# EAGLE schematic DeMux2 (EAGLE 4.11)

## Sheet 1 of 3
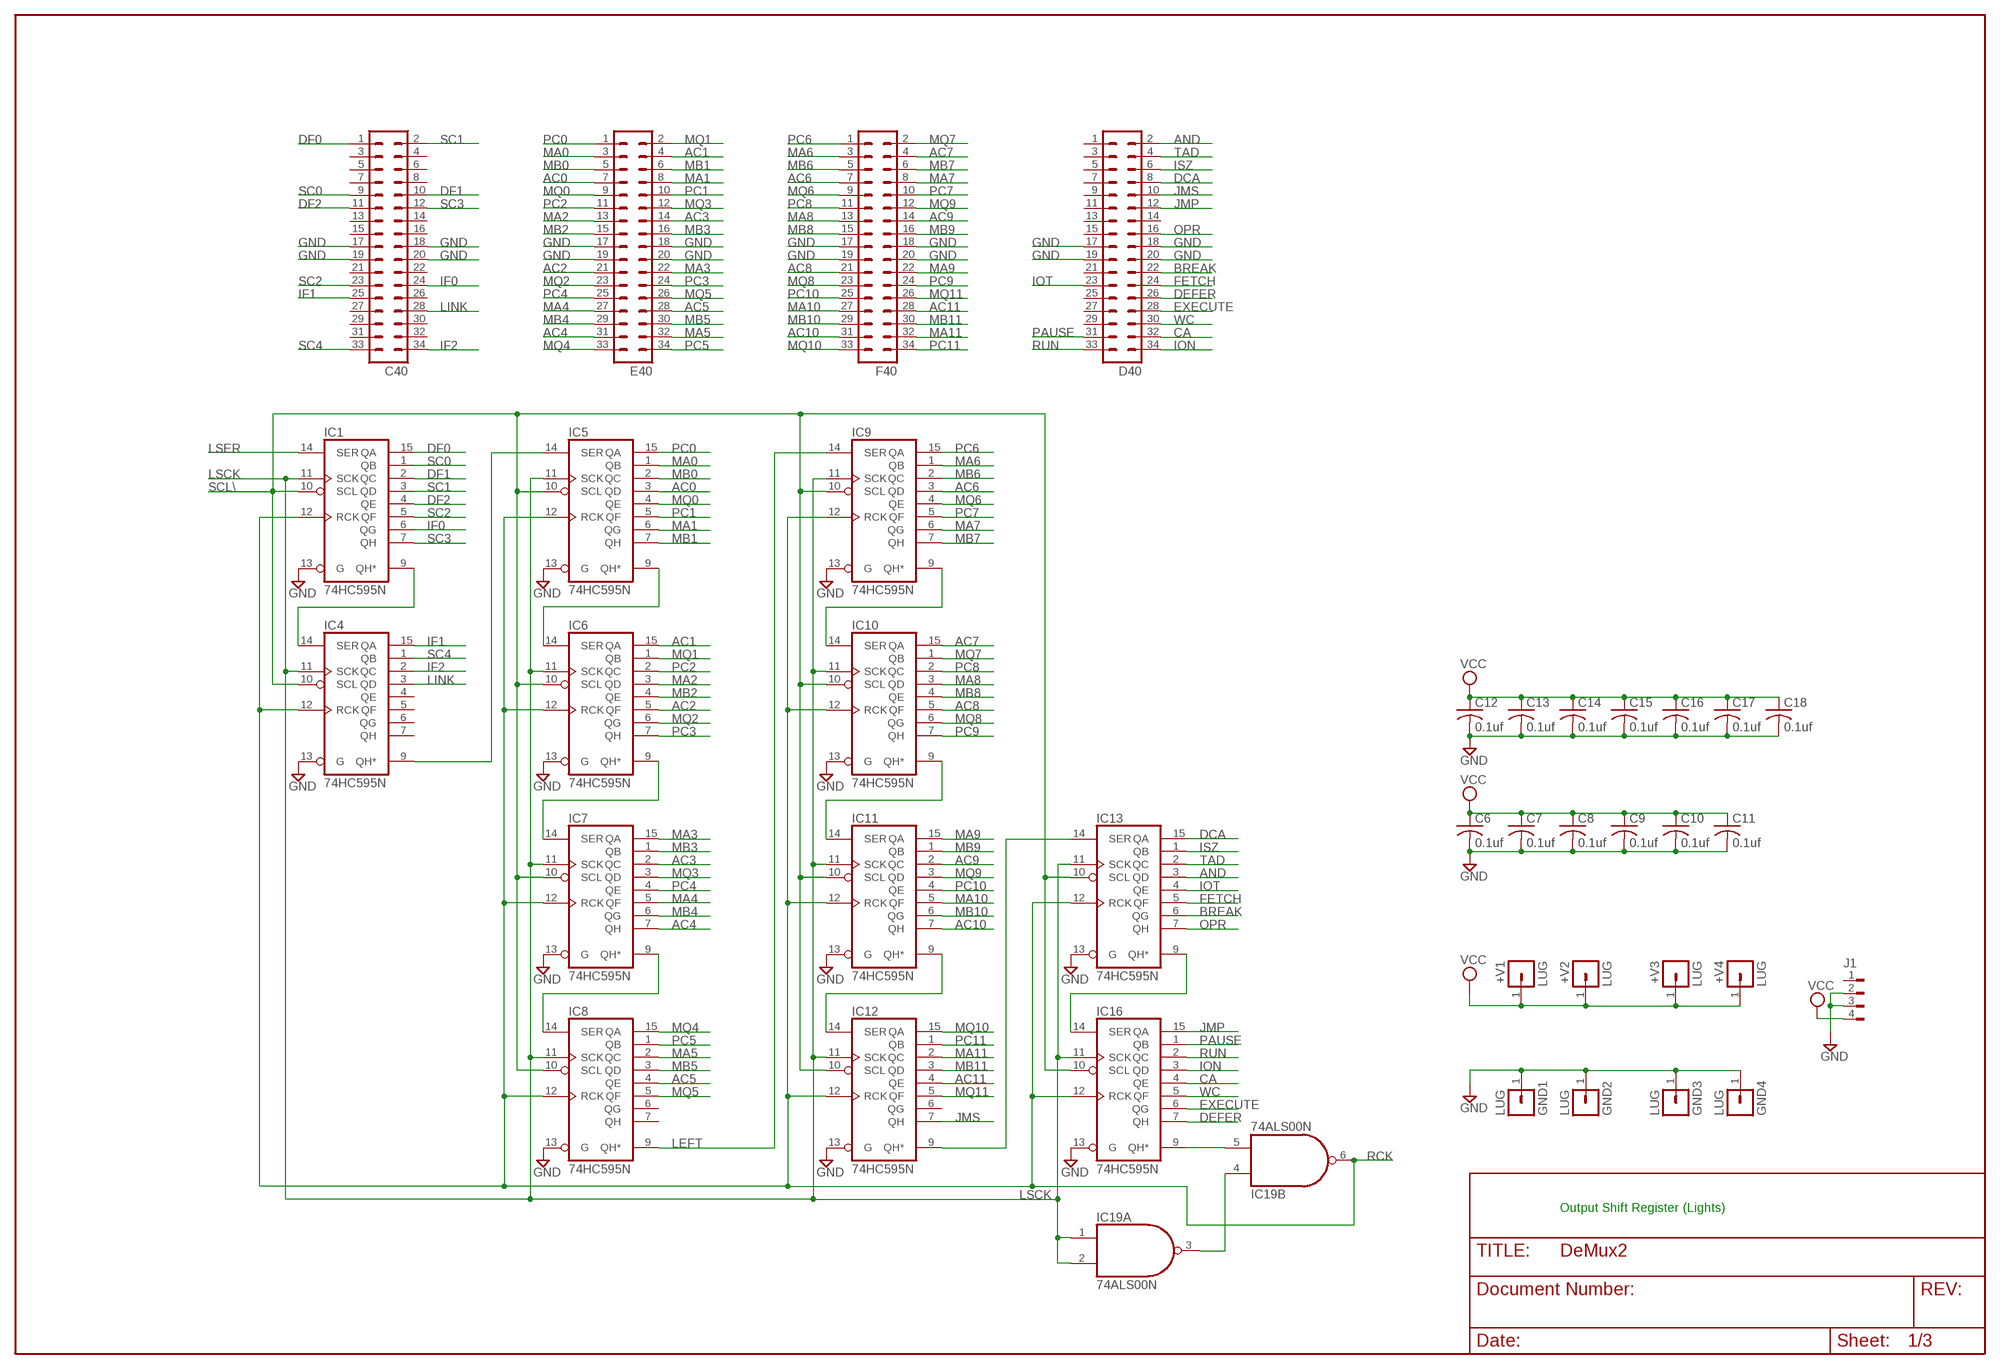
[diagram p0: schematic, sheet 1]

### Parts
+V1  LUG  [SPADELUG]
+V2  LUG  [SPADELUG]
+V3  LUG  [SPADELUG]
+V4  LUG  [SPADELUG]
C6  0.1uf  C-US050-025X075  [C050-025X075]
C7  0.1uf  C-US050-025X075  [C050-025X075]
C8  0.1uf  C-US050-025X075  [C050-025X075]
C9  0.1uf  C-US050-025X075  [C050-025X075]
C10  0.1uf  C-US050-025X075  [C050-025X075]
C11  0.1uf  C-US050-025X075  [C050-025X075]
C12  0.1uf  C-US050-025X075  [C050-025X075]
C13  0.1uf  C-US050-025X075  [C050-025X075]
C14  0.1uf  C-US050-025X075  [C050-025X075]
C15  0.1uf  C-US050-025X075  [C050-025X075]
C16  0.1uf  C-US050-025X075  [C050-025X075]
C17  0.1uf  C-US050-025X075  [C050-025X075]
C18  0.1uf  C-US050-025X075  [C050-025X075]
C40  MA17-2  [MA17-2]
D40  MA17-2  [MA17-2]
E40  MA17-2  [MA17-2]
F40  MA17-2  [MA17-2]
GND1  LUG  [SPADELUG]
GND2  LUG  [SPADELUG]
GND3  LUG  [SPADELUG]
GND4  LUG  [SPADELUG]
IC1  74HC595N  74LS595N  [DIL16]
IC4  74HC595N  74LS595N  [DIL16]
IC5  74HC595N  74LS595N  [DIL16]
IC6  74HC595N  74LS595N  [DIL16]
IC7  74HC595N  74LS595N  [DIL16]
IC8  74HC595N  74LS595N  [DIL16]
IC9  74HC595N  74LS595N  [DIL16]
IC10  74HC595N  74LS595N  [DIL16]
IC11  74HC595N  74LS595N  [DIL16]
IC12  74HC595N  74LS595N  [DIL16]
IC13  74HC595N  74LS595N  [DIL16]
IC16  74HC595N  74LS595N  [DIL16]
IC19  74ALS00N  [DIL14]
J1  FLOPPY-4  [FLOPPY-4]

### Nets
AC0: E40.7 IC5.3(QD)
AC1: E40.4 IC6.15(QA)
AC2: E40.21 IC6.5(QF)
AC3: E40.14 IC7.2(QC)
AC4: E40.31 IC7.7(QH)
AC5: E40.28 IC8.4(QE)
AC6: F40.7 IC9.3(QD)
AC7: F40.4 IC10.15(QA)
AC8: F40.21 IC10.5(QF)
AC9: F40.14 IC11.2(QC)
AC10: F40.31 IC11.7(QH)
AC11: F40.28 IC12.4(QE)
AND: D40.2 IC13.3(QD)
BREAK: D40.22 IC13.6(QG)
CA: D40.32 IC16.4(QE)
DCA: D40.8 IC13.15(QA)
DEFER: D40.26 IC16.7(QH)
DF0: C40.1 IC1.15(QA)
DF1: C40.10 IC1.2(QC)
DF2: C40.11 IC1.4(QE)
EXECUTE: D40.28 IC16.6(QG)
FETCH: D40.24 IC13.5(QF)
GND [supply]: C6.2 C7.2 C8.2 C9.2 C10.2 C11.2 C12.2 C13.2 C14.2 C15.2 C16.2 C17.2 C18.2 C40.17 C40.18 C40.19 C40.20 D40.17 D40.18 D40.19 D40.20 E40.17 E40.18 E40.19 E40.20 F40.17 F40.18 F40.19 F40.20 GND1.1 GND2.1 GND3.1 GND4.1 IC1.13(G) IC4.13(G) IC5.13(G) IC6.13(G) IC7.13(G) IC8.13(G) IC9.13(G) IC10.13(G) IC11.13(G) IC12.13(G) IC13.13(G) IC16.13(G) J1.2 J1.3 ; also sheet 2,3
IF0: C40.24 IC1.6(QG)
IF1: C40.25 IC4.15(QA)
IF2: C40.34 IC4.2(QC)
ION: D40.34 IC16.3(QD)
IOT: D40.23 IC13.4(QE)
ISZ: D40.6 IC13.1(QB)
JMP: D40.12 IC16.15(QA)
JMS: D40.10 IC12.7(QH)
LEFT: IC8.9(QH*) IC9.14(SER) ; also sheet 3
LINK: C40.28 IC4.3(QD)
LSCK: IC1.11(SCK) IC4.11(SCK) IC5.11(SCK) IC6.11(SCK) IC7.11(SCK) IC8.11(SCK) IC9.11(SCK) IC10.11(SCK) IC11.11(SCK) IC12.11(SCK) IC13.11(SCK) IC16.11(SCK) IC19.1(A:I0) IC19.2(A:I1) ; also sheet 3
LSER: IC1.14(SER) ; also sheet 3
MA0: E40.3 IC5.1(QB)
MA1: E40.8 IC5.6(QG)
MA2: E40.13 IC6.3(QD)
MA3: E40.22 IC7.15(QA)
MA4: E40.27 IC7.5(QF)
MA5: E40.32 IC8.2(QC)
MA6: F40.3 IC9.1(QB)
MA7: F40.8 IC9.6(QG)
MA8: F40.13 IC10.3(QD)
MA9: F40.22 IC11.15(QA)
MA10: F40.27 IC11.5(QF)
MA11: F40.32 IC12.2(QC)
MB0: E40.5 IC5.2(QC)
MB1: E40.6 IC5.7(QH)
MB2: E40.15 IC6.4(QE)
MB3: E40.16 IC7.1(QB)
MB4: E40.29 IC7.6(QG)
MB5: E40.30 IC8.3(QD)
MB6: F40.5 IC9.2(QC)
MB7: F40.6 IC9.7(QH)
MB8: F40.15 IC10.4(QE)
MB9: F40.16 IC11.1(QB)
MB10: F40.29 IC11.6(QG)
MB11: F40.30 IC12.3(QD)
MQ0: E40.9 IC5.4(QE)
MQ1: E40.2 IC6.1(QB)
MQ2: E40.23 IC6.6(QG)
MQ3: E40.12 IC7.3(QD)
MQ4: E40.33 IC8.15(QA)
MQ5: E40.26 IC8.5(QF)
MQ6: F40.9 IC9.4(QE)
MQ7: F40.2 IC10.1(QB)
MQ8: F40.23 IC10.6(QG)
MQ9: F40.12 IC11.3(QD)
MQ10: F40.33 IC12.15(QA)
MQ11: F40.26 IC12.5(QF)
N$4: IC5.9(QH*) IC6.14(SER)
N$10: IC1.9(QH*) IC4.14(SER)
N$13: IC7.9(QH*) IC8.14(SER)
N$14: IC6.9(QH*) IC7.14(SER)
N$15: IC11.9(QH*) IC12.14(SER)
N$16: IC10.9(QH*) IC11.14(SER)
N$17: IC13.9(QH*) IC16.14(SER)
N$19: IC9.9(QH*) IC10.14(SER)
N$21: IC4.9(QH*) IC5.14(SER)
N$22: IC16.9(QH*) IC19.5(B:I1)
N$23: IC12.9(QH*) IC13.14(SER)
N$27: IC19.3(A:O) IC19.4(B:I0)
OPR: D40.16 IC13.7(QH)
PAUSE: D40.31 IC16.1(QB)
PC0: E40.1 IC5.15(QA)
PC1: E40.10 IC5.5(QF)
PC2: E40.11 IC6.2(QC)
PC3: E40.24 IC6.7(QH)
PC4: E40.25 IC7.4(QE)
PC5: E40.34 IC8.1(QB)
PC6: F40.1 IC9.15(QA)
PC7: F40.10 IC9.5(QF)
PC8: F40.11 IC10.2(QC)
PC9: F40.24 IC10.7(QH)
PC10: F40.25 IC11.4(QE)
PC11: F40.34 IC12.1(QB)
RCK: IC1.12(RCK) IC4.12(RCK) IC5.12(RCK) IC6.12(RCK) IC7.12(RCK) IC8.12(RCK) IC9.12(RCK) IC10.12(RCK) IC11.12(RCK) IC12.12(RCK) IC13.12(RCK) IC16.12(RCK) IC19.6(B:O) ; also sheet 3
RUN: D40.33 IC16.2(QC)
SC0: C40.9 IC1.1(QB)
SC1: C40.2 IC1.3(QD)
SC2: C40.23 IC1.5(QF)
SC3: C40.12 IC1.7(QH)
SC4: C40.33 IC4.1(QB)
SCL\: IC1.10(SCL) IC4.10(SCL) IC5.10(SCL) IC6.10(SCL) IC7.10(SCL) IC8.10(SCL) IC9.10(SCL) IC10.10(SCL) IC11.10(SCL) IC12.10(SCL) IC13.10(SCL) IC16.10(SCL) ; also sheet 2,3
TAD: D40.4 IC13.2(QC)
VCC [supply]: +V1.1 +V2.1 +V3.1 +V4.1 C6.1 C7.1 C8.1 C9.1 C10.1 C11.1 C12.1 C13.1 C14.1 C15.1 C16.1 C17.1 C18.1 J1.4 ; also sheet 2,3
WC: D40.30 IC16.5(QF)
Unconnected: C40.3 C40.4 C40.5 C40.6 C40.7 C40.8 C40.13 C40.14 C40.15 C40.16 C40.21 C40.22 C40.26 C40.27 C40.29 C40.30 C40.31 C40.32 D40.1 D40.3 D40.5 D40.7 D40.9 D40.11 D40.13 D40.14 D40.15 D40.21 D40.25 D40.27 D40.29 IC4.4(QE) IC4.5(QF) IC4.6(QG) IC4.7(QH) IC8.6(QG) IC8.7(QH) IC12.6(QG) IC19.8(C:O) IC19.9(C:I0) IC19.10(C:I1) IC19.11(D:O) IC19.12(D:I0) IC19.13(D:I1) J1.1

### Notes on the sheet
- Output Shift Register (Lights)

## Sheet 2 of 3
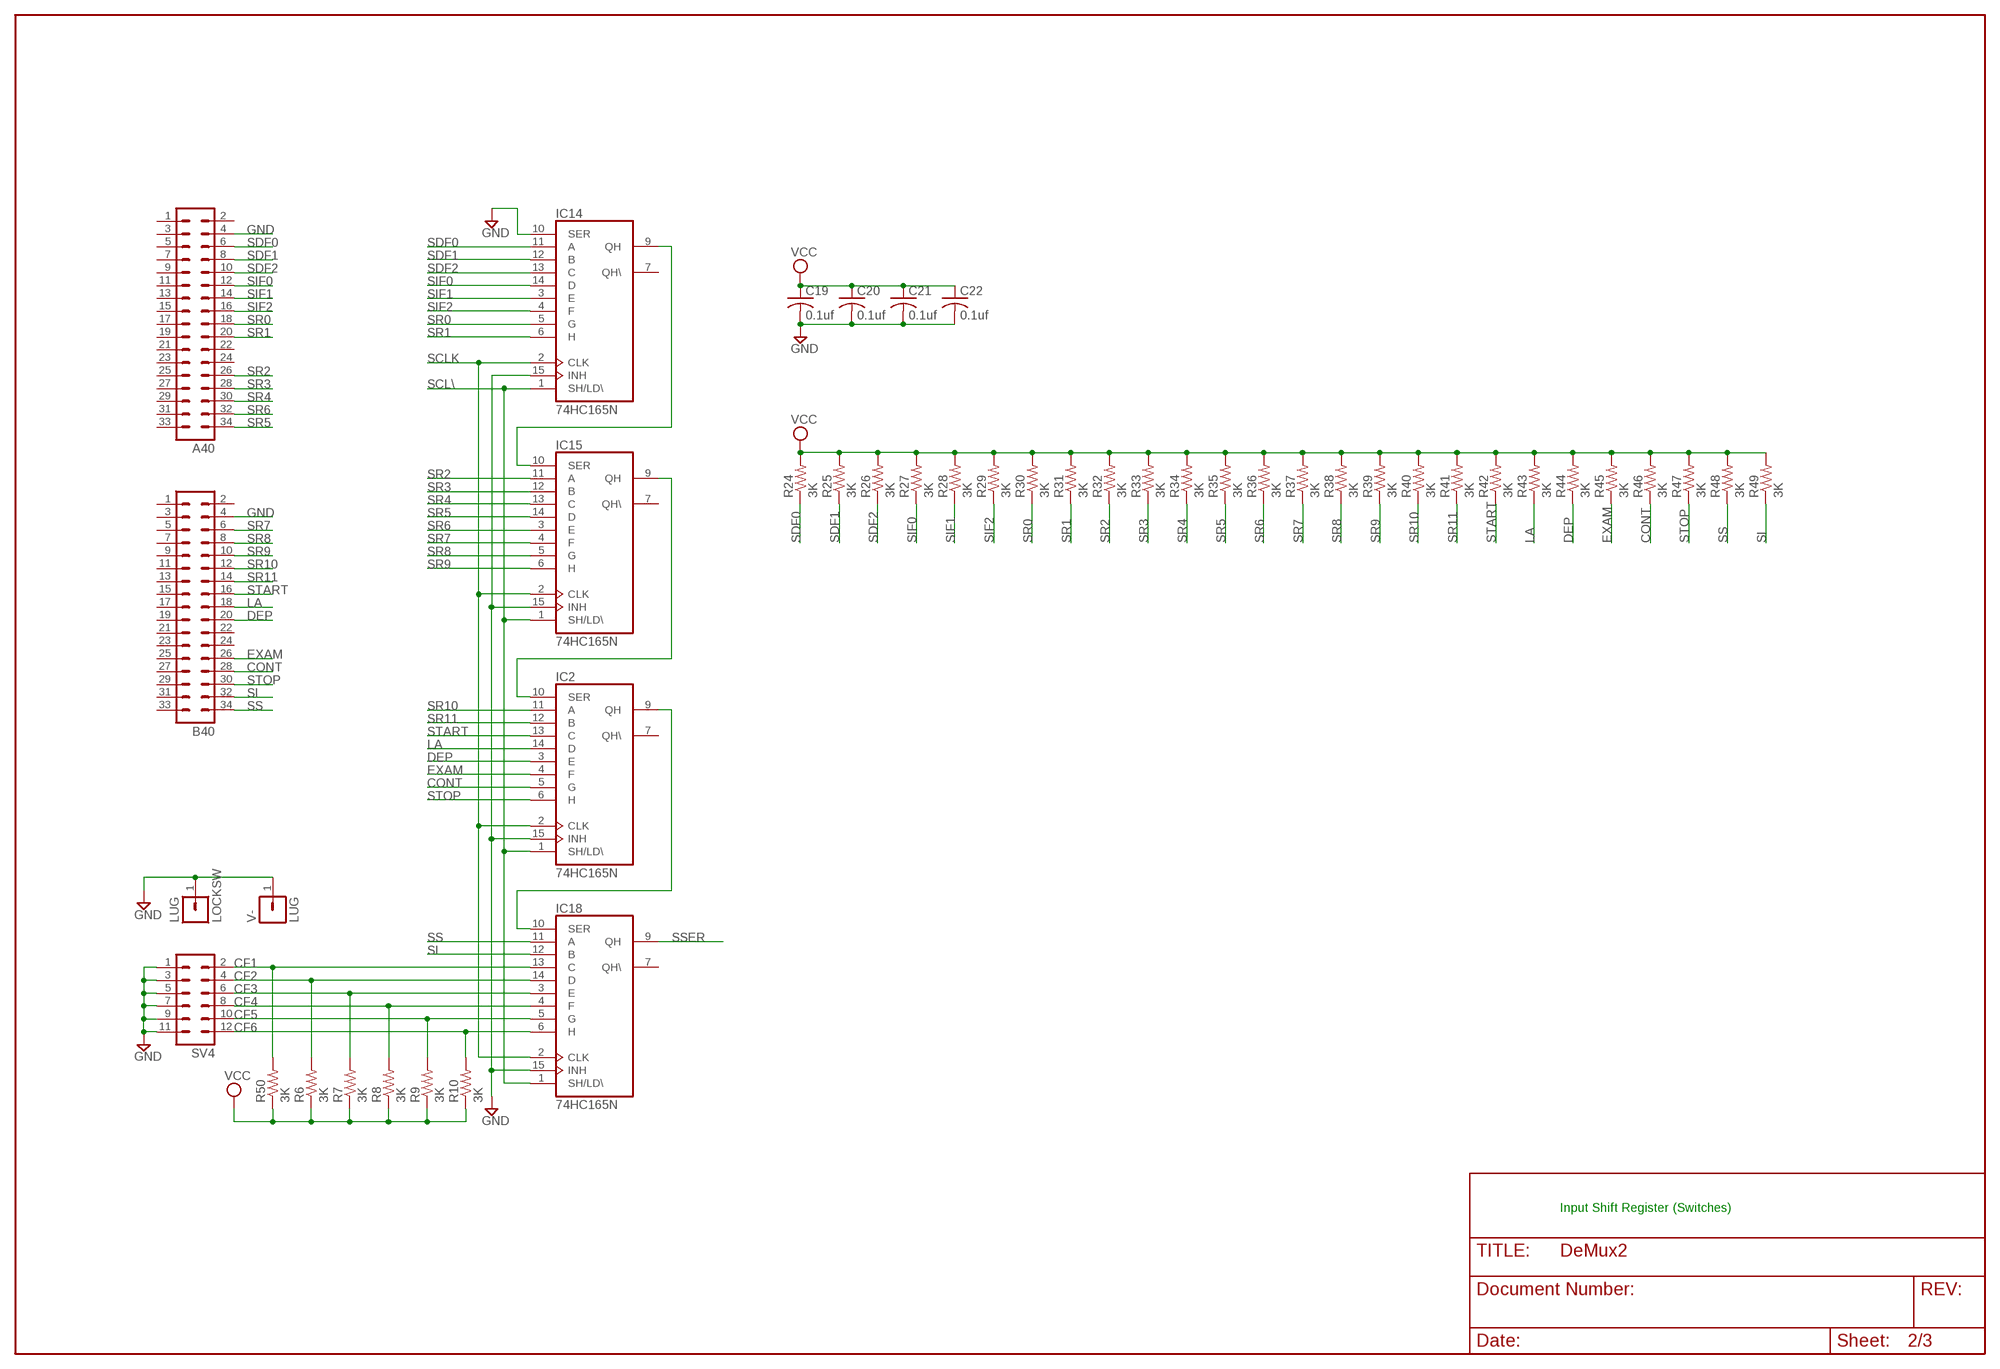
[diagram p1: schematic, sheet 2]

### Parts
A40  MA17-2  [MA17-2]
B40  MA17-2  [MA17-2]
C19  0.1uf  C-US050-025X075  [C050-025X075]
C20  0.1uf  C-US050-025X075  [C050-025X075]
C21  0.1uf  C-US050-025X075  [C050-025X075]
C22  0.1uf  C-US050-025X075  [C050-025X075]
IC2  74HC165N  74LS165N  [DIL16]
IC14  74HC165N  74LS165N  [DIL16]
IC15  74HC165N  74LS165N  [DIL16]
IC18  74HC165N  74LS165N  [DIL16]
LOCKSW  LUG  [SPADELUG]
R6  3K  R-US_0207/10  [0207/10]
R7  3K  R-US_0207/10  [0207/10]
R8  3K  R-US_0207/10  [0207/10]
R9  3K  R-US_0207/10  [0207/10]
R10  3K  R-US_0207/10  [0207/10]
R24  3K  R-US_0207/10  [0207/10]
R25  3K  R-US_0207/10  [0207/10]
R26  3K  R-US_0207/10  [0207/10]
R27  3K  R-US_0207/10  [0207/10]
R28  3K  R-US_0207/10  [0207/10]
R29  3K  R-US_0207/10  [0207/10]
R30  3K  R-US_0207/10  [0207/10]
R31  3K  R-US_0207/10  [0207/10]
R32  3K  R-US_0207/10  [0207/10]
R33  3K  R-US_0207/10  [0207/10]
R34  3K  R-US_0207/10  [0207/10]
R35  3K  R-US_0207/10  [0207/10]
R36  3K  R-US_0207/10  [0207/10]
R37  3K  R-US_0207/10  [0207/10]
R38  3K  R-US_0207/10  [0207/10]
R39  3K  R-US_0207/10  [0207/10]
R40  3K  R-US_0207/10  [0207/10]
R41  3K  R-US_0207/10  [0207/10]
R42  3K  R-US_0207/10  [0207/10]
R43  3K  R-US_0207/10  [0207/10]
R44  3K  R-US_0207/10  [0207/10]
R45  3K  R-US_0207/10  [0207/10]
R46  3K  R-US_0207/10  [0207/10]
R47  3K  R-US_0207/10  [0207/10]
R48  3K  R-US_0207/10  [0207/10]
R49  3K  R-US_0207/10  [0207/10]
R50  3K  R-US_0207/10  [0207/10]
SV4  MA06-2  [MA06-2]
V-  LUG  [SPADELUG]

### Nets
CF1: IC18.13(C) R50.2 SV4.2
CF2: IC18.14(D) R6.2 SV4.4
CF3: IC18.3(E) R7.2 SV4.6
CF4: IC18.4(F) R8.2 SV4.8
CF5: IC18.5(G) R9.2 SV4.10
CF6: IC18.6(H) R10.2 SV4.12
CONT: B40.28 IC2.5(G) R46.1
DEP: B40.20 IC2.3(E) R44.1
EXAM: B40.26 IC2.4(F) R45.1
GND [supply]: A40.4 B40.4 C19.2 C20.2 C21.2 C22.2 IC2.15(INH) IC14.10(SER) IC14.15(INH) IC15.15(INH) IC18.15(INH) LOCKSW.1 SV4.1 SV4.3 SV4.5 SV4.7 SV4.9 SV4.11 V-.1 ; also sheet 1,3
LA: B40.18 IC2.14(D) R43.1
N$1: IC14.9(QH) IC15.10(SER)
N$2: IC2.10(SER) IC15.9(QH)
N$3: IC2.9(QH) IC18.10(SER)
SCL\: IC2.1(SH/LD\) IC14.1(SH/LD\) IC15.1(SH/LD\) IC18.1(SH/LD\) ; also sheet 1,3
SCLK: IC2.2(CLK) IC14.2(CLK) IC15.2(CLK) IC18.2(CLK) ; also sheet 3
SDF0: A40.6 IC14.11(A) R24.1
SDF1: A40.8 IC14.12(B) R25.1
SDF2: A40.10 IC14.13(C) R26.1
SI: B40.32 IC18.12(B) R49.1
SIF0: A40.12 IC14.14(D) R27.1
SIF1: A40.14 IC14.3(E) R28.1
SIF2: A40.16 IC14.4(F) R29.1
SR0: A40.18 IC14.5(G) R30.1
SR1: A40.20 IC14.6(H) R31.1
SR2: A40.26 IC15.11(A) R32.1
SR3: A40.28 IC15.12(B) R33.1
SR4: A40.30 IC15.13(C) R34.1
SR5: A40.34 IC15.14(D) R35.1
SR6: A40.32 IC15.3(E) R36.1
SR7: B40.6 IC15.4(F) R37.1
SR8: B40.8 IC15.5(G) R38.1
SR9: B40.10 IC15.6(H) R39.1
SR10: B40.12 IC2.11(A) R40.1
SR11: B40.14 IC2.12(B) R41.1
SS: B40.34 IC18.11(A) R48.1
SSER: IC18.9(QH) ; also sheet 3
START: B40.16 IC2.13(C) R42.1
STOP: B40.30 IC2.6(H) R47.1
VCC [supply]: C19.1 C20.1 C21.1 C22.1 R6.1 R7.1 R8.1 R9.1 R10.1 R24.2 R25.2 R26.2 R27.2 R28.2 R29.2 R30.2 R31.2 R32.2 R33.2 R34.2 R35.2 R36.2 R37.2 R38.2 R39.2 R40.2 R41.2 R42.2 R43.2 R44.2 R45.2 R46.2 R47.2 R48.2 R49.2 R50.1 ; also sheet 1,3
Unconnected: A40.1 A40.2 A40.3 A40.5 A40.7 A40.9 A40.11 A40.13 A40.15 A40.17 A40.19 A40.21 A40.22 A40.23 A40.24 A40.25 A40.27 A40.29 A40.31 A40.33 B40.1 B40.2 B40.3 B40.5 B40.7 B40.9 B40.11 B40.13 B40.15 B40.17 B40.19 B40.21 B40.22 B40.23 B40.24 B40.25 B40.27 B40.29 B40.31 B40.33 IC2.7(QH\) IC14.7(QH\) IC15.7(QH\) IC18.7(QH\)

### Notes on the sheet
- Input Shift Register (Switches)

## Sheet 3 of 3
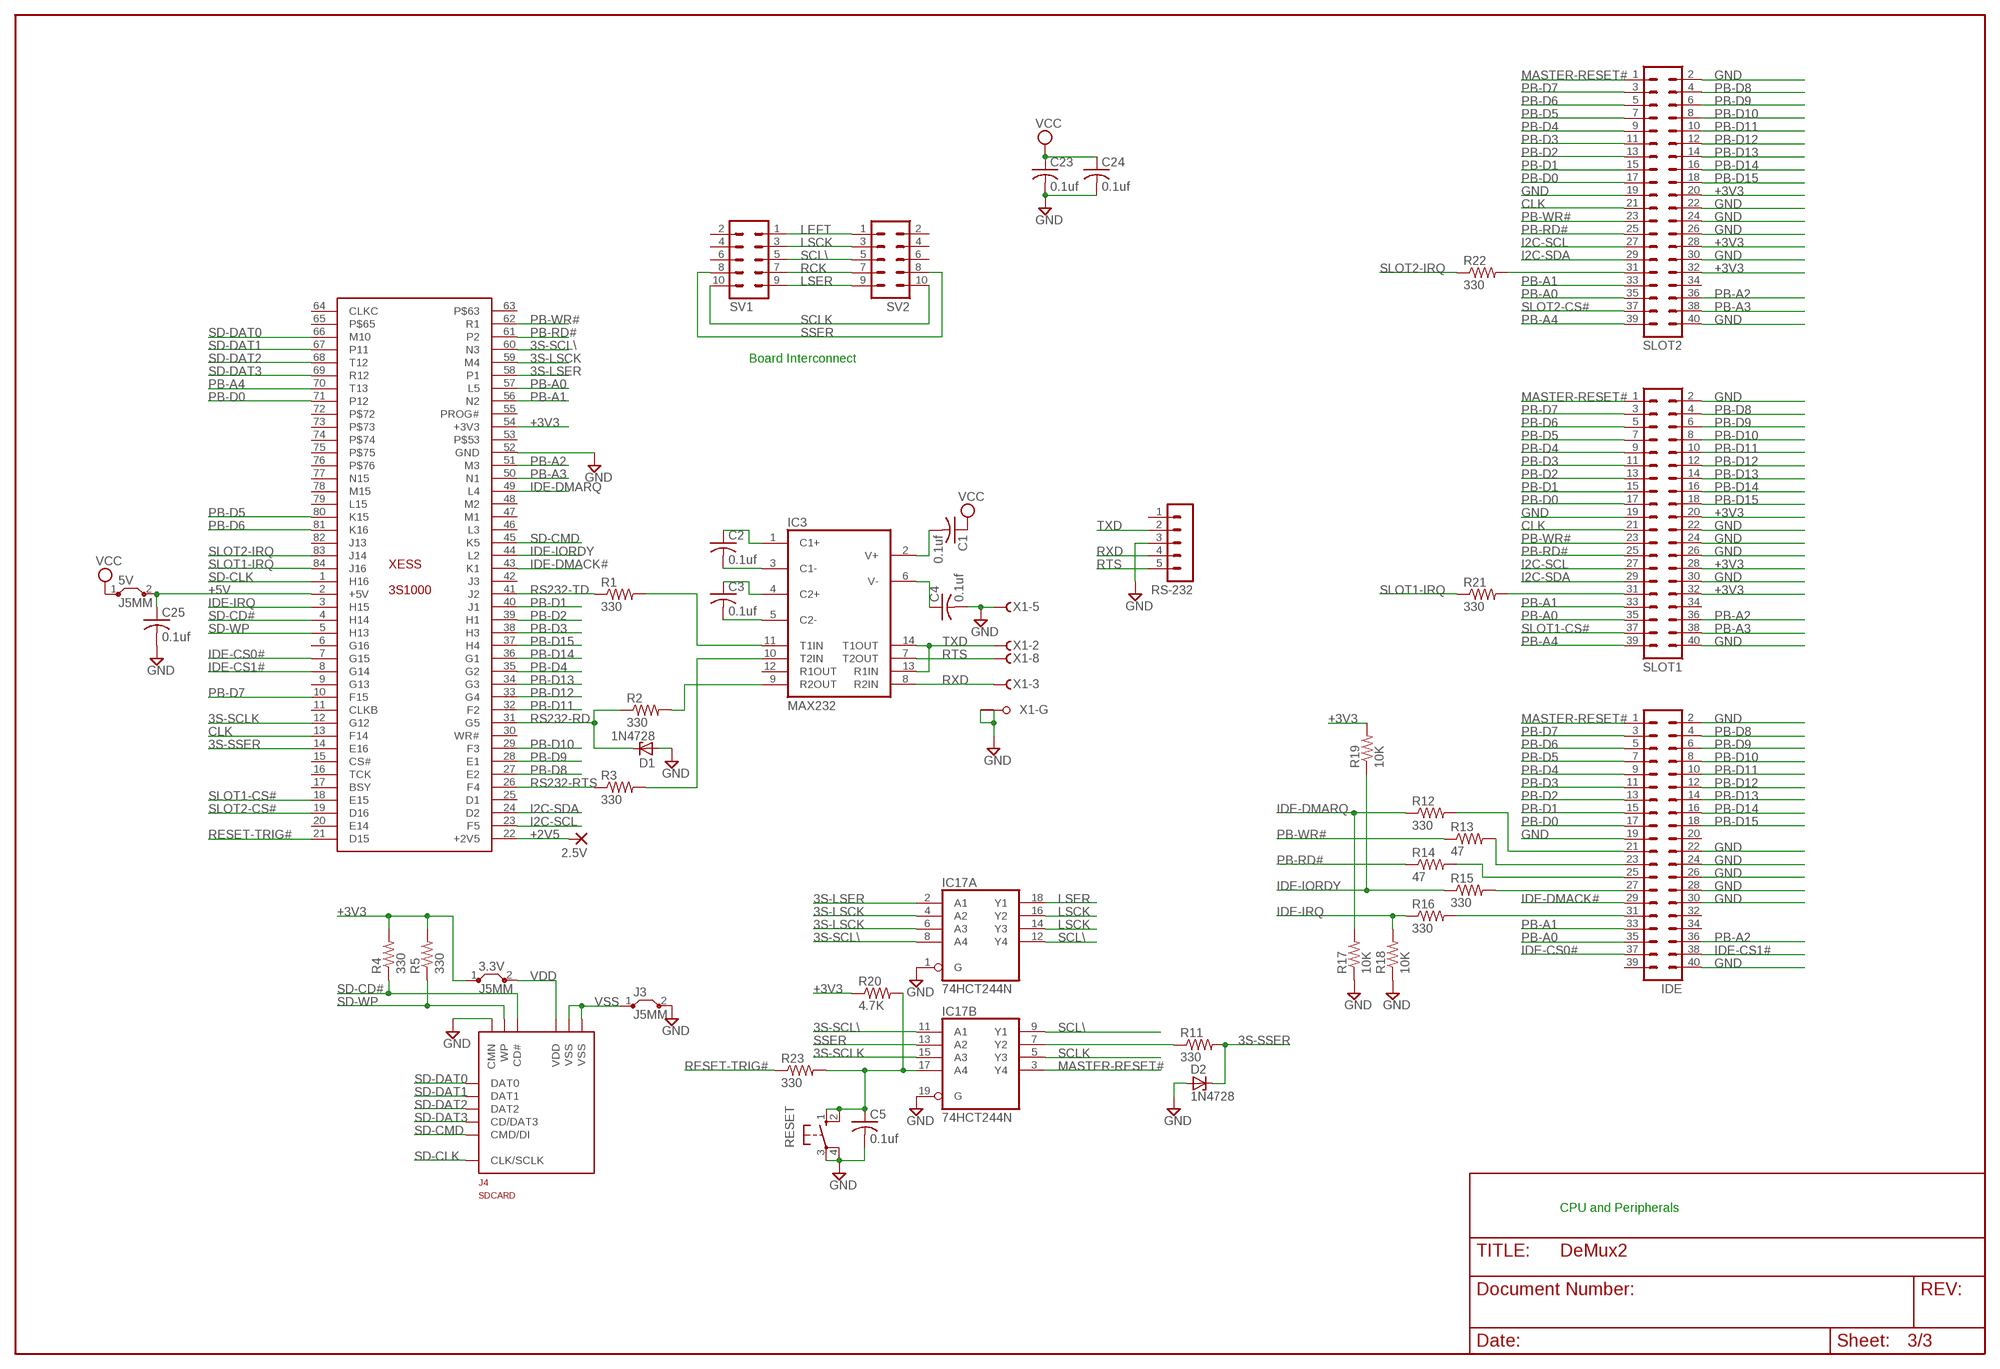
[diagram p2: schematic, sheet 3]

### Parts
2.5V  1,6/0,8  [1,6/0,8]
3.3V  J5MM  [05]
5V  J5MM  [05]
C1  0.1uf  C-US050-025X075  [C050-025X075]
C2  0.1uf  C-US050-025X075  [C050-025X075]
C3  0.1uf  C-US050-025X075  [C050-025X075]
C4  0.1uf  C-US050-025X075  [C050-025X075]
C5  0.1uf  C-US050-025X075  [C050-025X075]
C23  0.1uf  C-US050-025X075  [C050-025X075]
C24  0.1uf  C-US050-025X075  [C050-025X075]
C25  0.1uf  C-US050-025X075  [C050-025X075]
D1  1N4728  [DO41Z10]
D2  1N4728  [DO41Z10]
IC3  MAX232  [DIL16]
IC17  74HCT244N  [DIL20]
IDE  MA20-2  [MA20-2]
J3  J5MM  [05]
J4  SDCARD  [SCDA5A]
R1  330  R-US_0207/10  [0207/10]
R2  330  R-US_0207/10  [0207/10]
R3  330  R-US_0207/10  [0207/10]
R4  330  R-US_0207/10  [0207/10]
R5  330  R-US_0207/10  [0207/10]
R11  330  R-US_0207/10  [0207/10]
R12  330  R-US_0207/10  [0207/10]
R13  47  R-US_0207/10  [0207/10]
R14  47  R-US_0207/10  [0207/10]
R15  330  R-US_0207/10  [0207/10]
R16  330  R-US_0207/10  [0207/10]
R17  10K  R-US_0207/10  [0207/10]
R18  10K  R-US_0207/10  [0207/10]
R19  10K  R-US_0207/10  [0207/10]
R20  4.7K  R-US_0207/10  [0207/10]
R21  330  R-US_0207/10  [0207/10]
R22  330  R-US_0207/10  [0207/10]
R23  330  R-US_0207/10  [0207/10]
RESET  40-XX  [B3F-40XX]
RS-232  MA05-1  [MA05-1]
SLOT1  MA20-2  [MA20-2]
SLOT2  MA20-2  [MA20-2]
SV1  MA05-2  [MA05-2]
SV2  MA05-2  [MA05-2]
X1  F09HPS  [F09HP]
XESS  3S1000  [3S1000]

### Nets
3S-LSCK: IC17.4(A:A2) IC17.6(A:A3) XESS.59(M4)
3S-LSER: IC17.2(A:A1) XESS.58(P1)
3S-SCL\: IC17.8(A:A4) IC17.11(B:A1) XESS.60(N3)
3S-SCLK: IC17.15(B:A3) XESS.12(G12)
3S-SSER: D2.C R11.2 XESS.14(E16)
+2V5 [supply]: 2.5V.1(P) XESS.22(+2V5)
+3V3 [supply]: 3.3V.1 R4.2 R5.2 R19.2 R20.1 SLOT1.20 SLOT1.28 SLOT1.32 SLOT2.20 SLOT2.28 SLOT2.32 XESS.54(+3V3)
+5V [supply]: 5V.2 C25.1 XESS.2(+5V)
CLK: SLOT1.21 SLOT2.21 XESS.13(F14)
GND [supply]: C4.2 C5.2 C23.2 C24.2 C25.2 D1.A D2.A IC17.1(A:G) IC17.19(B:G) IDE.2 IDE.19 IDE.22 IDE.24 IDE.26 IDE.28 IDE.30 IDE.40 J3.2 J4.11(CMN) R17.1 R18.1 RESET.3(P) RESET.4(P1) RS-232.3 SLOT1.2 SLOT1.19 SLOT1.22 SLOT1.24 SLOT1.26 SLOT1.30 SLOT1.40 SLOT2.2 SLOT2.19 SLOT2.22 SLOT2.24 SLOT2.26 SLOT2.30 SLOT2.40 X1.5(-5:F) X1.G1(-G:G1) X1.G2(-G:G2) XESS.52(GND) ; also sheet 1,2
I2C-SCL: SLOT1.27 SLOT2.27 XESS.23(F5)
I2C-SDA: SLOT1.29 SLOT2.29 XESS.24(D2)
IDE-CS0#: IDE.37 XESS.7(G15)
IDE-CS1#: IDE.38 XESS.8(G14)
IDE-DMACK#: IDE.29 XESS.43(K1)
IDE-DMARQ: R12.1 R17.2 XESS.49(L4)
IDE-IORDY: R15.1 R19.1 XESS.44(L2)
IDE-IRQ: R16.1 R18.2 XESS.3(H15)
LEFT: SV1.1 SV2.1 ; also sheet 1
LSCK: IC17.14(A:Y3) IC17.16(A:Y2) SV1.3 SV2.3 ; also sheet 1
LSER: IC17.18(A:Y1) SV1.9 SV2.9 ; also sheet 1
MASTER-RESET#: IC17.3(B:Y4) IDE.1 SLOT1.1 SLOT2.1
N$5: IC3.10(T2IN) R3.2
N$6: IC3.11(T1IN) R1.2
N$7: IC3.9(R2OUT) R2.2
N$8: C1.2 IC3.2(V+)
N$9: C2.2 IC3.3(C1-)
N$11: C2.1 IC3.1(C1+)
N$12: C4.1 IC3.6(V-)
N$18: C3.1 IC3.4(C2+)
N$20: C3.2 IC3.5(C2-)
N$28: IC17.7(B:Y2) R11.1
N$29: R21.2 SLOT1.31
N$30: R22.2 SLOT2.31
N$31: C5.1 IC17.17(B:A4) R20.2 R23.2 RESET.1(S) RESET.2(S1)
N$52: IDE.31 R16.2
N$53: IDE.27 R15.2
N$54: IDE.25 R14.2
N$55: IDE.23 R13.2
N$56: IDE.21 R12.2
PB-A0: IDE.35 SLOT1.35 SLOT2.35 XESS.57(L5)
PB-A1: IDE.33 SLOT1.33 SLOT2.33 XESS.56(N2)
PB-A2: IDE.36 SLOT1.36 SLOT2.36 XESS.51(M3)
PB-A3: SLOT1.38 SLOT2.38 XESS.50(N1)
PB-A4: SLOT1.39 SLOT2.39 XESS.70(T13)
PB-D0: IDE.17 SLOT1.17 SLOT2.17 XESS.71(P12)
PB-D1: IDE.15 SLOT1.15 SLOT2.15 XESS.40(J1)
PB-D2: IDE.13 SLOT1.13 SLOT2.13 XESS.39(H1)
PB-D3: IDE.11 SLOT1.11 SLOT2.11 XESS.38(H3)
PB-D4: IDE.9 SLOT1.9 SLOT2.9 XESS.35(G2)
PB-D5: IDE.7 SLOT1.7 SLOT2.7 XESS.80(K15)
PB-D6: IDE.5 SLOT1.5 SLOT2.5 XESS.81(K16)
PB-D7: IDE.3 SLOT1.3 SLOT2.3 XESS.10(F15)
PB-D8: IDE.4 SLOT1.4 SLOT2.4 XESS.27(E2)
PB-D9: IDE.6 SLOT1.6 SLOT2.6 XESS.28(E1)
PB-D10: IDE.8 SLOT1.8 SLOT2.8 XESS.29(F3)
PB-D11: IDE.10 SLOT1.10 SLOT2.10 XESS.32(F2)
PB-D12: IDE.12 SLOT1.12 SLOT2.12 XESS.33(G4)
PB-D13: IDE.14 SLOT1.14 SLOT2.14 XESS.34(G3)
PB-D14: IDE.16 SLOT1.16 SLOT2.16 XESS.36(G1)
PB-D15: IDE.18 SLOT1.18 SLOT2.18 XESS.37(H4)
PB-RD#: R14.1 SLOT1.25 SLOT2.25 XESS.61(P2)
PB-WR#: R13.1 SLOT1.23 SLOT2.23 XESS.62(R1)
RCK: SV1.7 SV2.7 ; also sheet 1
RESET-TRIG#: R23.1 XESS.21(D15)
RS232-RD: D1.C R2.1 XESS.31(G5)
RS232-RTS: R3.1 XESS.26(F4)
RS232-TD: R1.1 XESS.41(J2)
RTS: IC3.7(T2OUT) RS-232.5 X1.8(-8:F)
RXD: IC3.8(R2IN) RS-232.4 X1.3(-3:F)
SCL\: IC17.9(B:Y1) IC17.12(A:Y4) SV1.5 SV2.5 ; also sheet 1,2
SCLK: IC17.5(B:Y3) SV1.10 SV2.10 ; also sheet 2
SD-CD#: J4.10(CD#) R4.1 XESS.4(H14)
SD-CLK: J4.5(CLK/SCLK) XESS.1(H16)
SD-CMD: J4.2(CMD/DI) XESS.45(K5)
SD-DAT0: J4.7(DAT0) XESS.66(M10)
SD-DAT1: J4.8(DAT1) XESS.67(P11)
SD-DAT2: J4.9(DAT2) XESS.68(T12)
SD-DAT3: J4.1(CD/DAT3) XESS.69(R12)
SD-WP: J4.12(WP) R5.1 XESS.5(H13)
SLOT1-CS#: SLOT1.37 XESS.18(E15)
SLOT1-IRQ: R21.1 XESS.84(J16)
SLOT2-CS#: SLOT2.37 XESS.19(D16)
SLOT2-IRQ: R22.1 XESS.83(J14)
SSER: IC17.13(B:A2) SV1.8 SV2.8 ; also sheet 2
TXD: IC3.13(R1IN) IC3.14(T1OUT) RS-232.2 X1.2(-2:F)
VCC [supply]: 5V.1 C1.1 C23.1 C24.1 ; also sheet 1,2
VDD [supply]: 3.3V.2 J4.4(VDD)
VSS [supply]: J3.1 J4.3(VSS) J4.6(VSS)
Unconnected: IC3.12(R1OUT) IDE.20 IDE.32 IDE.34 IDE.39 RS-232.1 SLOT1.34 SLOT2.34 SV1.2 SV1.4 SV1.6 SV2.2 SV2.4 SV2.6 X1.1(-1:F) X1.4(-4:F) X1.6(-6:F) X1.7(-7:F) X1.9(-9:F) XESS.6(G16) XESS.9(G13) XESS.11(CLKB) XESS.15(CS#) XESS.16(TCK) XESS.17(BSY) XESS.20(E14) XESS.25(D1) XESS.30(WR#) XESS.42(J3) XESS.46(L3) XESS.47(M1) XESS.48(M2) XESS.53 XESS.55(PROG#) XESS.63 XESS.64(CLKC) XESS.65 XESS.72 XESS.73 XESS.74 XESS.75 XESS.76 XESS.77(N15) XESS.78(M15) XESS.79(L15) XESS.82(J13)

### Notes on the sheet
- Board Interconnect
- CPU and Peripherals

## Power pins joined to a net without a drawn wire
GND: IC1.8(GND) IC2.8(GND) IC3.15(GND) IC4.8(GND) IC5.8(GND) IC6.8(GND) IC7.8(GND) IC8.8(GND) IC9.8(GND) IC10.8(GND) IC11.8(GND) IC12.8(GND) IC13.8(GND) IC14.8(GND) IC15.8(GND) IC16.8(GND) IC17.10(P:GND) IC18.8(GND) IC19.7(P:GND) J4.13(GND) J4.14(GND)
VCC: IC1.16(VCC) IC2.16(VCC) IC3.16(VCC) IC4.16(VCC) IC5.16(VCC) IC6.16(VCC) IC7.16(VCC) IC8.16(VCC) IC9.16(VCC) IC10.16(VCC) IC11.16(VCC) IC12.16(VCC) IC13.16(VCC) IC14.16(VCC) IC15.16(VCC) IC16.16(VCC) IC17.20(P:VCC) IC18.16(VCC) IC19.14(P:VCC)

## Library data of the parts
2.5V = wirepad:1,6/0,8: THROUGH-HOLE PAD
3.3V 5V J3 = jumper:J: Bridge
+V1-+V4 GND1-GND4 LOCKSW V- = dec-con:LUG: Spade Lug
A40 B40 C40 D40 E40 F40 = con-lstb:MA17-2: PIN HEADER
C1-C25 = rcl:C-US: CAPACITOR, American symbol
D1 D2 = diode:1N4728: Z DIODE
IC1 IC4-IC13 IC16 = 74xx-jameco:74*595: 8-bit SHIFT REGISTER, output latch
IC2 IC14 IC15 IC18 = 74xx-jameco:74*165: 8-bit parallel load SHIFT REGISTER
IC3 = maxim:MAX232: RS232 TRANSEIVER
IC17 = 74xx-jameco:74*244: Octal BUFFER and LINE DRIVER, 3-state
IC19 = 74xx-jameco:74*00: Quad 2-input NAND gate
IDE SLOT1 SLOT2 = con-lstb:MA20-2: PIN HEADER
J1 = con-amp:FLOPPY-4: MATE N-LOCK
J4 = sdcards:SDCARD: SD Card Holder
R1-R50 = rcl:R-US_: RESISTOR, American symbol
RESET = switch-omron:40-XX: OMRON SWITCH
RS-232 = con-lstb:MA05-1: PIN HEADER
SV1 SV2 = con-lstb:MA05-2: PIN HEADER
SV4 = con-lstb:MA06-2: PIN HEADER
X1 = con-subd:F09HPS: SUB-D
XESS = xess:3S1000

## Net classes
1 supply: width 0.762 mm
